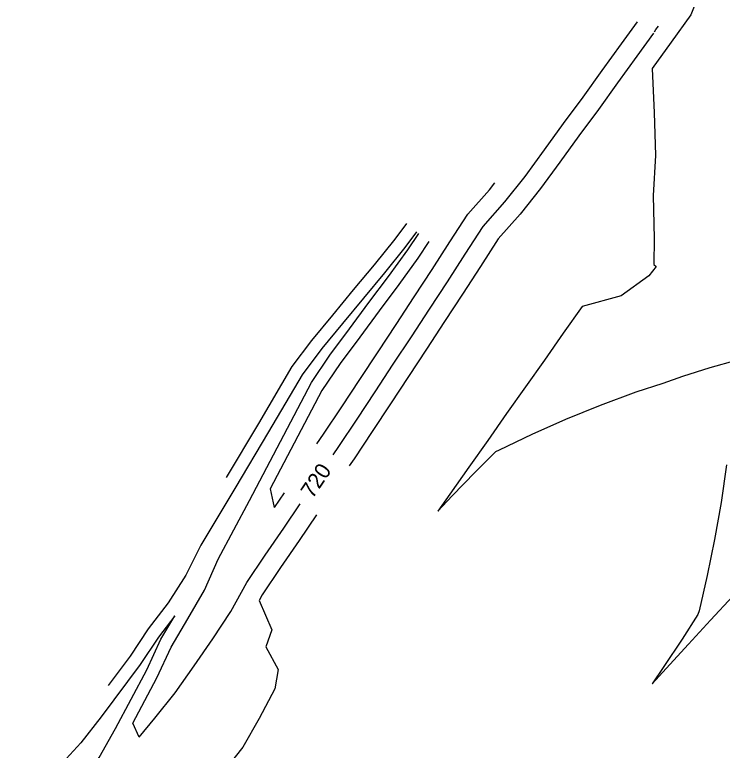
# Model space of a CAD drawing. Extents: x 1487507 to 1489130, y 497211 to 499439.
# Drawn here: x 1488547.6 to 1488655.8, y 498959.4 to 499071.8 of the extents above; entities that cross this region are included whole.
import ezdxf

# ---------------------------------------------------------------- set-up
doc = ezdxf.new("R2010")
doc.units = 0
for name, color, linetype in [('Prop CMT Ditch DDE', 7, 'Continuous'), ('Prop Drainage Ditch Flow Line', 7, 'Continuous'), ('Prop Drainage Structure Pipe Outlet Channel Detail CELL', 7, 'Continuous')]:
    doc.layers.add(name, color=color, linetype=linetype)

msp = doc.modelspace()

# ---------------------------------------------------------------- linework, layer by layer
at = {"layer": 'Prop CMT Ditch DDE'}
for points in [[(1488654.06, 499079.51), (1488650.96, 499071.8)], [(1488650.96, 499071.8), (1488647.98, 499067.64), (1488645.08, 499063.61), (1488645.08, 499063.55), (1488645.4, 499056.87), (1488645.58, 499050.31), (1488645.21, 499044.18), (1488645.4, 499037.6), (1488645.3, 499033.65), (1488645.69, 499033.34), (1488644.54, 499031.88), (1488640.35, 499028.83), (1488634.37, 499027.23), (1488631.48, 499023.13), (1488628.59, 499019.04), (1488625.71, 499014.94), (1488622.82, 499010.85), (1488619.93, 499006.75), (1488617.05, 499002.66), (1488614.16, 498998.56), (1488612.31, 498995.95), (1488614.52, 498998.27), (1488618.02, 499001.88), (1488621.17, 499005.05), (1488621.71, 499005.32), (1488626.72, 499007.71), (1488631.87, 499009.98), (1488637.16, 499012.13), (1488642.61, 499014.16), (1488646.74, 499015.52), (1488649.75, 499016.57), (1488653.92, 499017.88), (1488657.95, 499019.04)], [(1488645.41, 499069.2), (1488645.64, 499069.53), (1488646.02, 499070.06)], [(1488645.27, 499069.01), (1488642.72, 499065.46), (1488639.79, 499061.4), (1488636.85, 499057.35), (1488633.88, 499053.32), (1488630.94, 499049.27), (1488627.98, 499045.23), (1488624.88, 499041.31), (1488621.55, 499037.57), (1488618.83, 499033.34), (1488616.09, 499029.12), (1488613.35, 499024.91), (1488610.6, 499020.71), (1488607.84, 499016.51), (1488605.07, 499012.32), (1488602.29, 499008.13), (1488599.51, 499003.96), (1488598.78, 499002.86)], [(1488593.82, 499006.21), (1488594.84, 499007.72), (1488597.62, 499011.9), (1488600.4, 499016.08), (1488603.17, 499020.27), (1488605.93, 499024.47), (1488608.68, 499028.68), (1488611.42, 499032.89), (1488614.16, 499037.11), (1488616.88, 499041.33), (1488620.21, 499045.07), (1488621.04, 499046.13)], [(1488607.5, 499039.9), (1488605.71, 499037.49), (1488602.58, 499033.59), (1488599.39, 499029.75), (1488596.2, 499025.89), (1488593.02, 499022.04), (1488590.01, 499018.04), (1488584.88, 499009.33), (1488579.96, 499001.07)], [(1488610.94, 499037.13), (1488609.26, 499034.63), (1488606.34, 499030.57), (1488603.34, 499026.56), (1488600.36, 499022.54), (1488597.37, 499018.53), (1488594.56, 499014.37), (1488589.83, 499005.34), (1488586.67, 498999.37), (1488587.29, 498996.51)], [(1488656.44, 499003.01), (1488655.6, 498997.26), (1488654.62, 498991.63), (1488653.5, 498986.11), (1488652.23, 498980.71), (1488652.07, 498980.13), (1488649.64, 498976.37), (1488646.86, 498972.19), (1488645.05, 498969.54), (1488647.22, 498971.9), (1488650.61, 498975.59), (1488654, 498979.28), (1488657.39, 498982.97)], [(1488588.8, 498998.74), (1488587.29, 498996.51)], [(1488593.76, 498995.4), (1488591.1, 498991.47), (1488588.28, 498987.32), (1488585.47, 498983.16), (1488584.98, 498982.28), (1488586.92, 498977.8), (1488586.03, 498975.18), (1488587.92, 498971.73), (1488587.37, 498968.78), (1488585.02, 498964.26), (1488582.52, 498959.85), (1488579.37, 498955.96), (1488576.08, 498952.2), (1488571.38, 498949.56), (1488561.55, 498951.06), (1488561.07, 498950.67), (1488558.26, 498947.29), (1488555.08, 498943.43), (1488552.37, 498940.16)], [(1488552.37, 498940.16), (1488551.37, 498942.28), (1488557.8, 498954.09), (1488560.56, 498958.29), (1488563.03, 498962.72), (1488567.81, 498971.71), (1488569.98, 498976.39), (1488572.1, 498979.94), (1488572.09, 498979.95), (1488572.09, 498979.95), (1488569.6, 498976.69), (1488566.82, 498972.51), (1488560.83, 498964.49), (1488557.75, 498960.55), (1488554.38, 498956.85), (1488547.63, 498948.03)]]:
    msp.add_lwpolyline(points, dxfattribs=at)
at = {"layer": 'Prop Drainage Ditch Flow Line'}
for points in [[(1488596.3, 499004.54), (1488597.17, 499005.84), (1488599.96, 499010.02), (1488602.74, 499014.2), (1488605.5, 499018.39), (1488608.26, 499022.59), (1488611.01, 499026.79), (1488613.76, 499031.01), (1488616.49, 499035.22), (1488619.22, 499039.45), (1488622.54, 499043.19), (1488625.64, 499047.11), (1488628.6, 499051.15), (1488631.54, 499055.2), (1488634.51, 499059.23), (1488637.45, 499063.28), (1488640.38, 499067.34), (1488642.83, 499070.75)], [(1488609.06, 499038.65), (1488607.27, 499036.24), (1488604.14, 499032.34), (1488600.94, 499028.49), (1488597.76, 499024.64), (1488594.58, 499020.78), (1488591.56, 499016.79), (1488586.43, 499008.08), (1488581.27, 498999.4), (1488576.08, 498990.73), (1488573.79, 498986.15), (1488571.08, 498981.92), (1488568.05, 498977.94), (1488565.27, 498973.76), (1488561.91, 498969.28)], [(1488566.68, 498961.38), (1488565.67, 498963.51), (1488569.36, 498970.46), (1488571.53, 498975.13), (1488574.12, 498979.47), (1488576.64, 498983.86), (1488578.72, 498988.6), (1488583.51, 498997.59), (1488588.27, 499006.59), (1488593, 499015.62), (1488595.82, 499019.78), (1488598.8, 499023.8), (1488601.78, 499027.81), (1488604.78, 499031.82), (1488607.71, 499035.88), (1488609.38, 499038.39)], [(1488566.68, 498961.38), (1488569.04, 498964.29), (1488572.18, 498968.19), (1488575.04, 498972.3), (1488577.9, 498976.42), (1488580.67, 498980.61), (1488583.13, 498985.05), (1488585.94, 498989.2), (1488588.76, 498993.35), (1488591.28, 498997.07)]]:
    msp.add_lwpolyline(points, dxfattribs=at)

# ---------------------------------------------------------------- texts
at = {"layer": 'Prop Drainage Structure Pipe Outlet Channel Detail CELL'}
msp.add_text('720', height=2.4, rotation=56.0043, dxfattribs=at).set_placement((1488593.16, 498997.73))

doc.saveas('drawing.dxf')
